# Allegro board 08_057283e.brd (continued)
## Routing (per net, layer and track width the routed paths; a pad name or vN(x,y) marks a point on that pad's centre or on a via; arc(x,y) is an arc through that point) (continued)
LTC6563_ADJ1: length 79.4
  TOP w0.254: v1(41.12,29.21) 41.47,29.55 U4.23
  L4_SIGNAL w0.203: v1(99.31,45.33) 99.31,43.68 97.21,41.58 86.28,41.58 85.41,40.71 85.41,39.65 84.76,39 84.76,35.23 78.77,29.24 49.41,29.24 48.78,28.61 48.78,27.07 48.78,27.07 48.78,26.17 48.03,25.43 48.03,24.59 47.7,24.26 44.32,24.26 41.09,27.49 41.09,29.18 v1(41.12,29.21)
  BOTTOM w0.254: R20.2 R24.2 99.26,45.31 arc(99.28,45.32) v1(99.31,45.33)
LTC6563_CHSEL0: length 46.9
  TOP w0.254: U4.15 45.55,31.62 46.08,32.15 46.08,32.33 v1(46.11,32.35)
  L4_SIGNAL w0.203: v1(46.11,32.35) 46.11,32.37 47.02,33.27 48.47,33.27 58.15,42.95 82.64,42.95 82.84,43.15 v1(82.84,45.33)
  BOTTOM w0.254: v1(82.84,45.33) R28.1 R26.2
LTC6563_CHSEL1: length 47.7
  TOP w0.254: U4.13 46.55,31.33 47.14,31.92 47.14,32.03 v1(47.41,32.3)
  L4_SIGNAL w0.203: v1(47.41,32.3) 48.07,32.3 58.32,42.55 84.05,42.55 85.29,43.79 85.29,45.31 v1(85.31,45.33)
  BOTTOM w0.254: v1(85.31,45.33) R27.1 R25.2
LTC6563_CM: length 34.4
  TOP w0.203: C2.2 47.37,26.55 v1(46.53,27.39) 46.53,27.66 46.05,28.14 U4.7
  L4_SIGNAL w0.203: v1(65.07,41.91) 58.39,41.91 47.16,30.67 47.16,29.26 46.53,28.64 v1(46.53,27.39)
  BOTTOM w0.254: R10.2 R14.2 65.82,45.34 65.07,44.6 v1(65.07,41.91)
LTC6563_HI: length 46.2
  TOP w0.203: U4.8 46.55,28.22 47.32,27.45 v1(47.32,27.39) 48.05,27.39 48.44,27 C4.1
  L4_SIGNAL w0.203: v1(47.32,27.39) 47.56,27.63 47.56,30.51 58.43,41.38 65.3,41.38 65.83,41.91 v1(77.47,41.91)
  BOTTOM w0.254: R12.2 R16.2 77.72,45.34 77.47,45.09 v1(77.47,41.91)
LTC6563_O_MUX: length 58.9
  TOP w0.254: v1(45.87,27.39) 45.87,27.68 45.77,27.78 45.77,27.8 45.55,28.02 U4.6
  L4_SIGNAL w0.203: v1(91.05,45.33) 88.75,43.03 85.37,43.03 83.72,41.38 66.01,41.38 65.58,40.94 58.57,40.94 47.97,30.34 47.97,26.87 47.76,26.67 46.1,26.67 45.87,26.9 v1(45.87,27.39)
  BOTTOM w0.254: v1(91.05,45.33) R22.2 R18.2
LTC6563_OFFSET: length 39.2
  TOP w0.254: U4.16 45.05,31.97 v1(45.45,32.36)
  L4_SIGNAL w0.203: v1(73.53,45.34) 73.5,45.31 63.64,45.31 63.63,45.33 58.24,45.33 45.45,32.53 v1(45.45,32.36)
  BOTTOM w0.203: C3.2 46.79,33.1 46.58,32.89 45.98,32.89 45.97,32.89 45.89,32.89 45.57,32.57 45.57,32.49 v1(45.45,32.36)
  BOTTOM w0.254: v1(73.53,45.34) R15.2 R11.2
LTC6563_SHDN: length 65.4
  TOP w0.279: U4.4 44.55,27.58 v1(44.75,27.38)
  L4_SIGNAL w0.203: v1(95.12,45.33) 95.12,43.43 93.7,42.01 85.88,42.01 84.63,40.77 66.29,40.77 66.04,40.51 58.75,40.51 48.37,30.13 48.37,26.44 48.09,26.16 45.97,26.16 v1(44.75,27.38)
  BOTTOM w0.254: R17.2 R21.2 v1(95.12,45.33)
LTC6563_TILT: length 35.7
  TOP w0.254: v1(44.76,32.52) 44.76,32.46 44.55,32.26 44.55,31.2 U4.17
  L4_SIGNAL w0.203: v1(69.34,45.85) 58.08,45.85 v1(44.76,32.52)
  BOTTOM w0.203: v1(44.76,32.52) 45.74,33.51 C1.2
  BOTTOM w0.254: R9.2 R13.2 69.85,45.34 v1(69.34,45.85)
SPI_MISO: length 54.9
  TOP w0.305: U1.2 v1(25.81,48.16)
  L4_SIGNAL w0.254: P8.5 73.46,53.14 61.19,53.14 60.86,52.81 60.86,52.77 57.14,49.05 52.73,49.05 51.18,47.5 35.64,47.5 33.02,50.11 27.76,50.11 v1(25.81,48.16)
SPI_MOSI: length 77.6
  TOP w0.203: v1(61.42,52.58) 60.38,52.58 60.18,52.37 U2.6
  TOP w0.305: U1.3 v1(25.8,46.89)
  L4_SIGNAL w0.254: P8.4 77.22,52.96 76.83,52.58 v1(61.42,52.58) 56.72,47.88 53.17,47.88 52.33,47.04 33.71,47.04 33.15,46.48 26.21,46.48 v1(25.8,46.89)
  BOTTOM w0.254: v1(61.42,52.58) 62.46,52.58 63.5,51.54 76.66,51.54 77.21,52.09 R70.1 77.22,52.71 P8.4
SPI_SCK: length 65.7
  TOP w0.203: P8.6 72.31,54.18 72.31,52.86 71.65,52.2 65.76,52.2 65.39,51.82 U2.5
  TOP w0.305: U1.1 v1(25.8,49.43)
  L4_SIGNAL w0.254: v1(25.8,49.43) 26.94,50.57 33.21,50.57 34.54,49.25 35.84,48.01 50.75,48.01 53.16,50.42 57.86,50.42 60.4,52.96 60.4,54.71 61.8,56.11 70.38,56.11 P8.6
  BOTTOM w0.203: P8.6 72.13,54.35 R71.1
TEMP_CS: length 63.1
  TOP w0.305: U1.4 v1(25.8,45.62)
  L4_SIGNAL w0.254: v1(25.8,45.62) 26.15,45.97 33.29,45.97 33.9,46.58 61.16,46.58 65.53,50.95 78.89,50.95 P8.2
  BOTTOM w0.254: P8.2 82.3,54.35 R68.1
UNNAMED_4_ADLTC2634_I71_REF: length 6.8
  TOP w0.305: C27.2 58.77,51.6 59.05,51.32 U2.7
  TOP w0.457: C13.2 56.25,51.6 C27.2
  TOP w0.508: C13.2 56.23,54.37 REF.1
UNNAMED_4_ADT7311_I26_CT: length 2.1
  TOP w0.203: U1.6 30.88,46.89 R43.1
UNNAMED_4_ADT7311_I26_INT: length 2.1
  TOP w0.203: U1.5 30.85,45.62 R44.1
UNNAMED_4_CAP_I11_N2: length 2.6
  TOP w0.356: U3.8 56.58,14.21 C15.2 R45.2
UNNAMED_4_CAP_I12_N2: length 10.8
  TOP w0.406: U3.7 v1(55.13,12.74)
  BOTTOM w0.305: v1(55.13,12.74) 54.39,12 52.01,12 51.56,12.45 51.56,16.24 v1(50.08,17.73)
  vias: v1(48.68,18.36) v1(49.38,18.36) v1(49.38,17.73) v1(50.08,18.36) v1(62.57,4.75) v1(62.57,4.18) v1(64.52,4.75) v1(64.52,4.18)
UNNAMED_4_CNTP1P_I76_N1: length 5.3
  TOP w0.508: VIN.1 57.68,5.96 ; VIN.1 56.35,4.62 ; VIN.1 56.35,7.29 ; VIN.1 55.02,5.96
UNNAMED_4_DIOLED_I57_N: length 6.8
  TOP w0.406: U3.5 49.06,14.21 48.68,13.84 48.68,11.78 49.42,11.05 DS2.C
UNNAMED_4_DIOLED_I57_P: length 1.6
  TOP w0.406: DS2.A R63.1
UNNAMED_4_DIOLED_I60_P: length 1.6
  TOP w0.406: DS1.A R61.1
UNNAMED_4_IC24FC256_I37_WP: length 3.5
  BOTTOM w0.203: R58.1 62.4,45.9 R59.2 62.18,47.22 U5.7
UNNAMED_4_LINLT3045_I8_ILIM: length 1.4
  TOP w0.406: U3.6 49.67,13.56 R62.2
UNNAMED_6_ADLTC6563V2_I190_TERM: length 1.2
  TOP w0.279: U4.11 47.78,30.05 47.81,30.08 R47.2
UNNAMED_6_ADLTC6563V2_I190_TERMN: length 1.2
  TOP w0.279: U4.10 47.78,29.55 47.81,29.52 R48.1
UNNAMED_6_CAP_I2_N2: length 5.1
  TOP w0.254: U4.5 45.05,28.07 45.06,28.06 45.06,27.86 45.31,27.61 45.31,27.15 45.86,26.6 C18.2
  TOP w0.508: 46.38,24.18 46.37,24.17 E1.2 45.86,24.18 C17.2 45.86,25.36 C18.2
UNNAMED_6_CAP_I19_N1: length 60
  TOP w0.61: OUTBAR.1 68.12,20.91 arc(61.84,22.16) 56.52,25.72 R56.2 53.35,28.89 arc(53.33,28.9) C28.1 arc(53.09,29.05) 52.82,29.11 R54.2
UNNAMED_6_CAP_I19_N2: length 60
  TOP w0.61: R53.2 52.82,30.5 arc(53.09,30.55) C28.2 arc(53.45,30.73) 53.57,30.81 R55.1 56.79,34.04 arc(62,37.51) 68.14,38.73 68.18,38.69 OUT.1
UNNAMED_6_CAP_I24_N2: length 5.6
  TOP w0.254: 46.46,32.91 46.69,32.69 46.69,32.11 46.05,31.47 U4.14
  TOP w0.305: 46.46,32.91 C20.2
  TOP w0.508: 46.96,35.86 46.96,35.87 E2.1 46.44,35.87 C22.2 46.46,34.32 C20.2
UNNAMED_6_CN2P_I184_N2: length 8.1
  TOP w0.254: P13.2 89.23,49.68 89.47,49.44 89.47,46.09 89.23,45.85 CHSEL1.2
  BOTTOM w0.254: P13.2 88.09,49.63 R25.1
UNNAMED_6_CN2P_I185_N2: length 8.1
  TOP w0.254: SHDN.2 97.36,45.85 97.6,46.09 97.6,49.44 97.36,49.68 P14.2
  BOTTOM w0.254: P14.2 96.22,49.63 R17.1
UNNAMED_6_CN2P_I186_N2: length 8.1
  TOP w0.254: MUX.2 93.29,45.85 93.54,46.09 93.54,49.44 93.29,49.68 P15.2
  BOTTOM w0.254: P15.2 92.15,49.63 R18.1
UNNAMED_6_CN2P_I187_N2: length 8.1
  TOP w0.254: P21.2 101.55,49.68 101.79,49.44 101.79,46.09 101.55,45.85 ADJ1.2
  BOTTOM w0.254: P21.2 100.41,49.63 R20.1
UNNAMED_6_CN2P_I188_N2: length 8.1
  TOP w0.254: ADJ0.2 105.61,45.85 105.85,46.09 105.85,49.44 105.61,49.68 P20.2
  BOTTOM w0.254: P20.2 104.47,49.63 R19.1
UNNAMED_6_CN2P_I189_N2: length 8
  TOP w0.254: P19.2 85.17,49.68 85.41,49.44 85.41,46.36 84.9,45.85 CHSEL0.2
  BOTTOM w0.254: P19.2 84.03,49.63 R26.1
UNNAMED_6_CN3P_I173_N1: length 2.8
  BOTTOM w0.203: TILT.1 P2.1
UNNAMED_6_CN3P_I173_N2: length 3.3
  BOTTOM w0.305: P2.2 70.76,48.17 70.55,48.39 R9.1
UNNAMED_6_CN3P_I175_N1: length 2.8
  BOTTOM w0.203: P1.1 CM.1
UNNAMED_6_CN3P_I175_N2: length 3.3
  BOTTOM w0.305: P1.2 66.83,48.17 66.61,48.39 R10.1
UNNAMED_6_CN3P_I176_N1: length 2.8
  BOTTOM w0.203: P3.1 OFFSET.1
UNNAMED_6_CN3P_I176_N2: length 3.3
  BOTTOM w0.305: R11.1 74.36,48.39 74.57,48.17 P3.2
UNNAMED_6_CN3P_I177_N1: length 2.8
  BOTTOM w0.203: P4.1 HI.1
UNNAMED_6_CN3P_I177_N2: length 3.3
  BOTTOM w0.305: P4.2 78.38,48.17 78.17,48.39 R12.1
UNNAMED_6_DIOPHOTO6PV3_I91_A: length 2.3
  TOP w0.66: R34.2 D4.PAD
UNNAMED_6_DIOPHOTO6PV3_I91_C: length 2.2
  TOP w0.305: R42.1 37.14,17.69 36.24,17.69 36.24,17.7 D4.1
UNNAMED_6_DIOPHOTO6PV3_I92_A: length 2.3
  TOP w0.61: D3.PAD R33.2
UNNAMED_6_DIOPHOTO6PV3_I92_C: length 2.2
  TOP w0.305: D3.1 34.97,25.75 37.14,25.75 R41.1
UNNAMED_6_DIOPHOTO6PV3_I99_A: length 2.3
  TOP w0.61: D2.PAD R32.2
UNNAMED_6_DIOPHOTO6PV3_I99_C: length 2.2
  TOP w0.305: R40.1 37.15,33.78 36.24,33.78 36.24,33.79 D2.1
UNNAMED_6_DIOPHOTO6PV3_I100_A: length 2.3
  TOP w0.61: D1.PAD R31.2
UNNAMED_6_DIOPHOTO6PV3_I100_C: length 2.2
  TOP w0.305: D1.1 36.24,41.83 36.24,41.84 36.25,41.83 R39.1
UNNAMED_6_FERRITE_I43_N2: length 1.6
  TOP w0.508: R50.1 45.47,35.89 E2.2 44.94,35.87 44.93,35.86
UNNAMED_6_FERRITE_I44_N1: length 1.6
  TOP w0.508: R46.2 44.9,23.1 E1.1 44.38,24.17 44.37,24.18
UNNAMED_6_RES_I13_N2: length 2.3
  TOP w0.279: R52.1 49.14,28.89 R48.2 47.81,28.89 47.65,29.05 U4.9
UNNAMED_6_RES_I14_N1: length 2.3
  TOP w0.279: R51.1 49.14,30.72 R47.1 47.81,30.72 47.65,30.55 U4.12
UNNAMED_6_RES_I15_N2: length 0.8
  TOP w0.61: R52.2 R54.1
UNNAMED_6_RES_I20_N2: length 0.8
  TOP w0.61: R51.2 R53.1
UNNAMED_6_RES_I48_N2: length 22.5
  BOTTOM w0.508: R8.2 43.21,25.15 43.89,25.15 R4.2
  BOTTOM w0.61: R67.1 43.55,22.97 arc(43.87,21.37) 44.78,20.02 46.54,18.26 arc(48.36,15.53) 49,12.32 49,6.11 arc(49,6.07) IN4.1
UNNAMED_6_RES_I58_N2: length 23.3
  TOP w0.508: R3.2 41.67,26.34 41.62,26.29 41.57,26.34 R7.2
  TOP w0.61: IN3.1 37.41,9.42 arc(38.11,12.39) 39.61,15.04 arc(39.8,15.27) 40.01,15.5 arc(41.2,17.38) 41.62,19.57 41.62,27.5 R66.1
UNNAMED_6_RES_I64_N2: length 23.4
  TOP w0.508: R6.2 41.66,33.23 41.62,33.27 41.28,33.27 R2.2
  TOP w0.61: IN2.1 37.41,50.27 arc(38.11,47.3) 39.61,44.65 arc(39.8,44.42) 40.01,44.19 arc(41.2,42.31) 41.62,40.12 41.62,32.09 arc(41.62,32.07) R65.1
UNNAMED_6_RES_I69_N2: length 22.7
  BOTTOM w0.61: 49,53.52 49,53.59 IN1.1 arc(48.98,53.59) 49,53.52 ; 49,53.52 49,47.29 arc(48.36,44.07) 46.54,41.35 44.78,39.59 arc(43.87,38.23) 43.55,36.63 43.55,34.42 ; R5.2 43.92,34.42 43.55,34.42 ; 43.55,34.42 R64.1 ; 43.55,34.42 43.18,34.42 R1.2

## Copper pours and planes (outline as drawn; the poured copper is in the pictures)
+5V_DC2026C_VOUT on TOP: 65.61,5.08 65.61,3.28 65.74,3.15 82.09,3.15 82.37,3.43 82.37,10.64 82.14,10.87 78.82,10.87 78.61,10.67 78.61,7.98 78.18,7.54 67.06,7.54 66.93,7.42 66.93,5.21 66.8,5.08
GND on TOP: 110.74,58.93 110.74,39.62 106.68,39.62 106.68,37.85 110.74,37.85 110.74,21.84 106.68,21.84 106.68,19.94 110.74,19.94 110.74,1.52 83.31,1.52 52.96,1.52 52.96,1.52 1.52,1.52 1.02,2.03 1.02,26.54 4.06,26.54 4.06,33.02 1.02,33.02 1.02,58.55 1.4,58.93 43.94,58.93 ; 5 cut-outs
GND on BOTTOM: 1.02,58.93 110.74,58.93 110.74,1.02 109.21,1.02 1.02,1.02 ; 1 cut-out
GND on L2_GND, L4_SIGNAL: 1.9,58.04 109.85,58.04 109.85,1.9 1.9,1.9
GND on L3_VCC: 1.9,58.04 109.85,58.04 109.85,1.9 1.9,1.9 ; 1 cut-out
GND on L5_GND: 1.02,58.93 110.74,58.93 110.74,1.02 109.21,1.02 1.02,1.02
VCCI on TOP: 47.98,23.44 48.62,22.81 51.66,22.81 51.73,22.75 51.73,20.97 51.66,20.9 49.57,20.9 47.6,18.94 47.6,17.73 47.47,17.6 45.69,17.6 45.68,17.61 45.25,17.61 44.96,17.91 44.96,23.24 45.16,23.44
VCCO on TOP (solid shape): 33.3,49.87 33.3,48.67 33.24,48.6 32.28,48.6 31.78,49.11 28.47,49.11 28.28,49.3 28.28,49.75 28.47,49.94 33.24,49.94
VCCO on TOP: 52.68,22.87 52.68,20.9 52.74,20.84 54.78,20.84 54.84,20.78 54.84,17.41 54.71,17.28 54.71,15.32 58.2,15.32 58.46,15.57 58.46,21.31 56.9,22.87
VCCO on L3_VCC: 66.61,55.56 105.22,55.56 105.22,43.57 105.15,43.5 52.7,43.5 51.37,42.17 51.37,27.68 58.48,20.57 58.48,17.34 52.96,17.34 51.24,19.05 51.24,21.09 47.43,24.9 47.43,34.68 46.49,35.62 44.2,35.62 43.75,36.07 43.75,43.31 42.3,44.77 29.98,44.77 27.37,47.38 27.37,52.77 33.34,52.77 33.34,49.09 66.61,49.09
DC2026C_VIN on TOP: 62.26,8.62 62.38,8.75 64.8,8.75 64.92,8.62 64.92,6.02 64.86,5.96 62.38,5.96 62.26,6.08
DC2026C_VIN on BOTTOM: 62.28,14.07 62.28,6.2 62.66,5.82 67.28,5.82 69.8,8.33 87.71,8.33 87.71,4.85 87.68,4.83 87.68,4.34 87.96,4.06 91.08,4.06 91.64,4.62 91.64,13.87 91.03,14.48 62.69,14.48
UNNAMED_4_CAP_I12_N2 on TOP: 64.99,3.48 64.73,3.23 62.57,3.23 62.32,3.48 62.32,5 62.38,5.07 64.86,5.07 64.99,4.94
UNNAMED_4_CAP_I12_N2 on TOP: 51.16,18.55 51.16,17.6 51.35,17.41 51.35,14.74 51.22,14.62 48.43,14.62 48.11,14.94 48.11,18.36 48.36,18.62 51.09,18.62
UNNAMED_4_CAP_I12_N2 on L3_VCC: 48.65,18.61 50.8,18.61 52.7,16.7 58.67,16.7 64.96,10.41 64.96,3.87 58.61,3.87 58.61,9.15 56.65,11.11 49.41,11.11 48.58,11.94 48.58,18.54
UNNAMED_4_CNTP1P_I76_N1 on TOP: 61.62,8.69 61.62,3.73 61.49,3.61 53.94,3.61 53.68,3.86 53.68,8.75 53.94,9 61.3,9
UNNAMED_6_CAP_I75_N2 on TOP (solid shape): 13.92,30.68 14.96,30.68 14.96,28.93 13.92,28.93 13.31,28.32 5.03,28.32 4.88,28.47 4.88,31.04 5.11,31.27 13.34,31.27
UNNAMED_6_CAP_I107_N2 on TOP (solid shape): 29.54,40.31 22.89,40.31 22.76,40.18 22.76,33.35 22.78,33.32 29.57,33.32 29.57,32.26 22.78,32.26 22.76,32.23 22.76,25.3 22.78,25.27 29.57,25.27 29.57,24.21 22.76,24.21 22.76,17.35 22.89,17.22 29.57,17.22 29.57,16.18 22.45,16.18 21.72,16.92 21.72,40.61 22.48,41.38 29.54,41.38
UNNAMED_6_RES_I77_N2 on TOP (solid shape): 19.76,28.93 16.89,28.93 16.89,30.68 19.76,30.68

Small or netless copper shapes (teardrops, artwork), in the pictures only: 4 on TOP

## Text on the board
User.Comments: CR_3_1 | CR_3_2 | CR_3_3 | CR_1_3 | CR_1_2 | CR_2_4 | WIRE ENTRY | 5.    INSTALL SHUNT CONNECTOR (M026786) TO THE FOLLOWING JUMPER CONNECTORS. | 6.    DO NOT TRIM EXCESS LEAD FOR P8, P9, P10, P11. | 4.    RoHS COMPLIANCE: ASSEMBLY VENDOR SHOULD ASSURE COMPLIANCE | PIN 2 AND 3 OF P1, P2, P3, P4. | PIN 1 AND 2 OF P13, P14, P15, P19, P20, P21 | WITH LEAD-FREE AND RoHS PCB ASSEMBLY STANDARDS (EU RoHS | DIRECTIVE 2002/95/EC).
Ref Des/Silkscreen Top: C | A | B | EVAL-LTC6563-TQFN
PAGE_OUTLINE: N/A | A | B | B1 | C | D | E | INITIAL RELEASE | AS PER ECR-090443 | AS PER ECR-091439 | AS PER ECR-099516 | AS PER ECR-100326 | AS PER ECR-105524 | 20JUN19 | 08OCT19 | 09JAN20 | 29OCT20 | 22NOV20 | 16NOV21 | JVILLANUEVA | CGOZON | HHASHEMI | EVALUATION BOARD Z
DIMENSION: (REF) | - | " " | DIA MAX
User.11: C | A
User.15: NELCO 4000-13 EP | ISOLA 370HR | ROHS COMPLIANCE NOTE:  HOMOGENOUS MATERIALS IN THIS BOARD SHALL BE COMPLIANT | THE EU RoHS DIRECTIVE 2002/95/EC | 15.    BOARDS TO BE SHIPPED IN ARRAYS AND KEEP INTACT | PANEL TO BE SUBJECTED TO CUSTOMER'S APPROVAL | L3_VCC PLANE  (LAYER 3)
User.17: L2 GND | 08-      -07
User.18: L3 VCC | 08-      -08
User.19: L4_SIG | 08-      -09
User.20: L5 GND | 08-      -10
User.45: FIGURE | SIZE | 8.0 | 12.0 | 30.0 | 40.0 | 45.0 | 60.0 | 63.0 | 65.0 | 35.0 | PLATED | NON-PLATED | DRILL CHART: TOP to BOTTOM | ALL UNITS ARE IN MILS | QTY | 323 | 321 | 42 | 8 | 32 | 2 | 3 | 20 | TOLERANCE/NOTES
